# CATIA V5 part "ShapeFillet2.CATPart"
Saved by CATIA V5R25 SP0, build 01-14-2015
Part number: Part1
Bounding box of the stored display mesh (mm): x 2636.87 to 2658.584, y 475.412 to 576.341, z 2218.144 to 2468.369
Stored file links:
  E:\cadcim\GSD_cat_v5-6r2014\Part_files\ShapeFillet2.CATPart
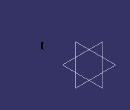
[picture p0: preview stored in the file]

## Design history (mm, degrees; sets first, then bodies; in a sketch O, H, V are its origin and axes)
Set1
  DatumSurface1 to DatumSurface4
  Fillet1: type BiTangent, Element1 DatumSurface2, Element2 DatumSurface1, Radius 3
  Trim1: Element1 DatumSurface3, Element2 Fillet1
  Fillet2: type BiTangent, Element1 DatumSurface4, Element2 Trim1, Radius 4, FacesToKeep face of Fillet1
Body1 (main body)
